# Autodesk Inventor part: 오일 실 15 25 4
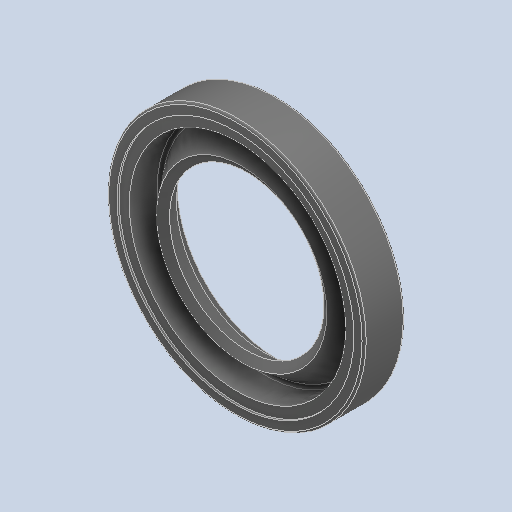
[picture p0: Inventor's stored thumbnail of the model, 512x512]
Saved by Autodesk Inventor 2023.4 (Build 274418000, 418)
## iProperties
Created: 2024-10
Part Number: 오일 실 15 25 4
Material: 고무
Description: 오일 실 - 비스프링, 조립 GA
Document SubType Name: Modeling
Designer: EDU
Density: 0.93 g/cm^3
Appearance: 기본값
Author: jhkim
Sending System: Autodesk Inventor 2025
Preprocessor: ST-DEVELOPER v20
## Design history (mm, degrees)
feature "Solid1"
node "솔리드1"
